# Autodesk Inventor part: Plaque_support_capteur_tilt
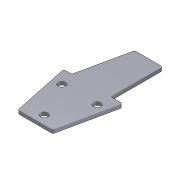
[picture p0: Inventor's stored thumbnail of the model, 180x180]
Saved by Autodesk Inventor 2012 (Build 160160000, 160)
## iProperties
Created: 2011-01
Part Number: Plaque_support_capteur_tilt
Document SubType Name: Modeling
Designer: eric
Density: 1 g/cm^3
Mass: 2.75433 g
Surface Area: 31.7477 cm^2
Volume: 2.75433 cm^3
Material: Par défaut
Author: eric
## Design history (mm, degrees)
feature "Base1"
node "Corps solides"
node "Corps surfaciques"
node "Solide1"
